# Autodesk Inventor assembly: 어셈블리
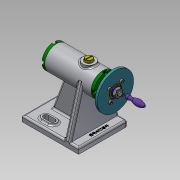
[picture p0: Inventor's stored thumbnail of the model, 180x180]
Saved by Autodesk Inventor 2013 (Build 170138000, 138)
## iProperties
Created: 2019-10
Part Number: 어셈블리
Document SubType Name: Assembly
Designer: hana-max10
Author: hana-max10
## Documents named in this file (18)
- C:\Documents and Settings\hana-max10\바탕 화면\491004V1025\어셈블리.iam
- C:\Documents and Settings\hana-max10\바탕 화면\491004V1025\본체.ipt
- C:\Documents and Settings\hana-max10\바탕 화면\491004V1025\나사.ipt
- C:\Documents and Settings\hana-max10\바탕 화면\491004V1025\나사축.ipt
- C:\Documents and Settings\hana-max10\바탕 화면\491004V1025\너트 M8.ipt
- C:\Documents and Settings\hana-max10\바탕 화면\491004V1025\돌림판.ipt
- C:\Documents and Settings\hana-max10\바탕 화면\491004V1025\멈춤나사 M3.ipt
- C:\Documents and Settings\hana-max10\바탕 화면\491004V1025\볼트 M3.ipt
- C:\Documents and Settings\hana-max10\바탕 화면\491004V1025\부시.ipt
- C:\Documents and Settings\hana-max10\바탕 화면\491004V1025\센터.ipt
- C:\Documents and Settings\hana-max10\바탕 화면\491004V1025\센터홀더.ipt
- C:\Documents and Settings\hana-max10\바탕 화면\491004V1025\슬리브.ipt
- C:\Documents and Settings\hana-max10\바탕 화면\491004V1025\와셔.ipt
- C:\Documents and Settings\hana-max10\바탕 화면\491004V1025\중공축.ipt
- C:\Documents and Settings\hana-max10\바탕 화면\491004V1025\커버.ipt
- C:\Documents and Settings\hana-max10\바탕 화면\491004V1025\키 4 x 4 x 10.ipt
- C:\Documents and Settings\hana-max10\바탕 화면\491004V1025\플랜지.ipt
- C:\Documents and Settings\hana-max10\바탕 화면\491004V1025\핸들.ipt
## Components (2 placed, 2 different names)
1. 플랜지:1 — 플러쉬:1
2. 핸들:1
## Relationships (1: Flush 1)
- 플러쉬:1 [Flush]: 플랜지:1
